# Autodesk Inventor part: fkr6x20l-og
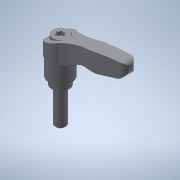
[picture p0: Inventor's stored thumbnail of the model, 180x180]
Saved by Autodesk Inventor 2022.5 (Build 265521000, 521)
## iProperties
Created: 2017-09
Part Number: fkr6x20l-og
Material: 一般
Document SubType Name: Modeling
Designer: imaocorp
Density: 1 g/cm^3
Appearance: 既定
Author: imaocorp
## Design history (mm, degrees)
node "fkr6x20l-og.x_t1"
node "fkr6x20l-og"
node "Base1"
